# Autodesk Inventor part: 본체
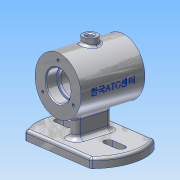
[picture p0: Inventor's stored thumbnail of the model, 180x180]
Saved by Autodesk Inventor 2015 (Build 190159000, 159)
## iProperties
Created: 2017-12
Part Number: 본체
Material: 알루미늄 6061
Document SubType Name: Modeling
Designer: user
Density: 2.7 g/cm^3
Appearance: 알루미늄 - 평지
Mass: 465.966 g
Surface Area: 486.474 cm^2
Volume: 172.58 cm^3
Author: user
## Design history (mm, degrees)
sketch "스케치1"
  geometry: C1 r 30 at (0, 0); 1 further point
  constraints: 1 centre point, 1 coincident
  dimensions: "d0" = 60 diameter of C1
extrude "돌출1" new body sketch "스케치1" stored distance "d1" = 70; taper "d2" = 0 deg
node "작업 평면1"
sketch "스케치2"
  geometry: L1 (-42.426, 35)-(42.426, 35); L2 (42.426, -35)-(-42.426, -35); L3 (-71.542, 35)-(71.542, -35); L4 (71.542, 35)-(-71.542, -35); A1 r 55 centre (0, 0) between (-42.426, 35) and (-42.426, -35); A2 r 55 centre (0, 0) between (42.426, -35) and (42.426, 35); 1 further point
  constraints: 8 end point, 4 point on circle, 2 centre point, 2 midpoint, 1 coincident, 1 horizontal, 1 parallel
  dimensions: "d5" = 70 distance between parallel lines of L2 L1; "d6" = 110 diameter of A2
extrude "돌출2" join sketch "스케치2" distance "d15" = 10; taper "d16" = 0 deg
sketch "스케치3"
  geometry: L1 (42.426, -35)-(-42.426, -35) reference; L2 (-42.426, 35)-(42.426, 35) reference; L3 (0, -15)-(0, 15); L4 (5, -15)-(5, 15); L5 (-5, 15)-(-5, -15); A1 r 55 centre (0, 0) between (-42.426, 35) and (-42.426, -35) reference; A2 r 55 centre (0, 0) between (42.426, -35) and (42.426, 35) reference; A3 r 55 centre (0, 0) between (-42.426, 35) and (-42.426, -35) reference; A4 r 5 centre (0, -15) between (-5, -15) and (5, -15); A5 r 5 centre (0, 15) between (5, 15) and (-5, 15); 1 further point
  constraints: 8 end point, 4 point on circle, 4 tangent, 2 centre point, 1 coincident, 1 midpoint, 1 parallel, 1 vertical
  dimensions: "d17" = 10 diameter of A5; "d18" = 30 distance of L3.end L3.start
extrude "돌출3" join sketch "스케치3" stored distance "d19" = 10; taper "d20" = 0 deg
sketch "스케치4"
  geometry: L1 (24, 0)-(40, 0); L2 (24, -5)-(40, -5); L3 (40, 5)-(24, 5); L4 (-24, 0)-(-40, 0); L5 (-24, 5)-(-40, 5); L6 (-40, -5)-(-24, -5); A1 r 55 centre (0, 0) between (-42.426, 35) and (-42.426, -35) reference; A2 r 5 centre (24, 0) between (24, 5) and (24, -5); A3 r 5 centre (40, 0) between (40, -5) and (40, 5); A4 r 5 centre (-24, 0) between (-24, -5) and (-24, 5); A5 r 5 centre (-40, 0) between (-40, 5) and (-40, -5); 2 further points
  constraints: 16 end point, 8 point on circle, 8 tangent, 4 centre point, 2 horizontal, 2 horizontal alignment, 2 midpoint, 2 parallel
  dimensions: "d21" = 10 diameter of A3; "d22" = 10 diameter of A5; "d23" = 24 distance of L4.start A1.centre; "d24" = 16 distance of L4.start L4.end; "d25" = 24 distance of L1.start A1.centre; "d26" = 16 distance of L1.end L1.start
extrude "돌출4" cut sketch "스케치4" stored distance "d27" = 10; taper "d28" = 0 deg
hole "구멍1" diameter "d31" = 32; stored, may be unused: countersink angle "d35" = 90 deg, drill point angle "d37" = 0 deg; dims "d32" = 6, "d33" = 4, "d34" = 2, "d36" = 12, "d38" = 10, "d39" = 10
hole "구멍2" diameter "d42" = 28; stored, may be unused: countersink angle "d46" = 90 deg, drill point angle "d48" = 0 deg; dims "d40" = 10, "d41" = 10, "d43" = 6, "d44" = 4, "d45" = 2, "d47" = 3
hole "구멍3" diameter "d51" = 50; stored, may be unused: countersink angle "d55" = 90 deg, drill point angle "d57" = 0 deg; dims "d49" = 10, "d50" = 10, "d52" = 6, "d53" = 4, "d54" = 2, "d56" = 40
hole "구멍4" diameter "d60" = 28; stored, may be unused: countersink angle "d64" = 90 deg, drill point angle "d66" = 0 deg; dims "d58" = 10, "d59" = 10, "d61" = 6, "d62" = 4, "d63" = 2, "d65" = 3
hole "구멍5" diameter "d69" = 32; stored, may be unused: countersink angle "d73" = 90 deg, drill point angle "d75" = 0 deg; dims "d67" = 10, "d68" = 10, "d70" = 6, "d71" = 4, "d72" = 2, "d74" = 12
node "작업 평면2"
sketch "스케치6"
  geometry: C1 r 8 at (0, 0); 1 further point
  constraints: 1 centre point, 1 coincident
  dimensions: "d77" = 16 diameter of C1
extrude "돌출5" join sketch "스케치6" stored distance "d78" = 10; taper "d79" = 0 deg
hole "구멍6" diameter "d82" = 8; stored, may be unused: countersink angle "d86" = 90 deg, drill point angle "d88" = 0 deg; dims "d80" = 10, "d81" = 10, "d83" = 6, "d84" = 4, "d85" = 2, "d87" = 12
chamfer "모따기1" distance "d89" = 1; stored, may be unused: second distance "d90" = 2, angle "d91" = 45 deg
fillet "모깎기1" dims "d92" = 5
fillet "모깎기2" dims "d93" = 5
fillet "모깎기3" dims "d94" = 3
fillet "모깎기4" dims "d95" = 3
fillet "모깎기5" dims "d96" = 3
chamfer "모따기2" distance "d97" = 1; stored, may be unused: second distance "d98" = 2, angle "d99" = 45 deg
chamfer "모따기3" distance "d100" = 1; stored, may be unused: second distance "d101" = 2, angle "d102" = 45 deg
fillet "모깎기6" dims "d103" = 0.3
sketch "스케치7" dims "d104" = 46
  geometry: C1 r 30 at (0, 0) reference; C2 r 17 at (0, 0) reference; 2 further points
  constraints: 2 vertical alignment, 1 coincident, 2 other
hole "구멍7" sketch "스케치7" at (0, 23) diameter "d105" = 3.242; stored, may be unused: countersink angle "d109" = 90 deg, drill point angle "d111" = 118 deg; dims "d106" = 8, "d107" = 4, "d108" = 2, "d110" = 10
node "작업 평면3"
sketch "스케치8" dims "d6" = 110
  geometry: L1 (30, 35)-(-30, 35) reference; 2 further points
  constraints: 1 other
  dimensions: "d116" = 35 distance from line of point (0, 0) L1; "d117" = 30 horizontal distance of point (0, 0) L1.start
feature "엠보싱1" sketch "스케치8" dims "d118" = 0.5, "d119" = 0
fillet "모깎기7" dims "d120" = 3
node "솔리드1"
pattern_circular "원형 패턴1" dims angle "d113" = 360 deg
mirror "대칭1"
node "절단 모서리 투영1"
other parameters: "d3" = -62, "d76" = 37
